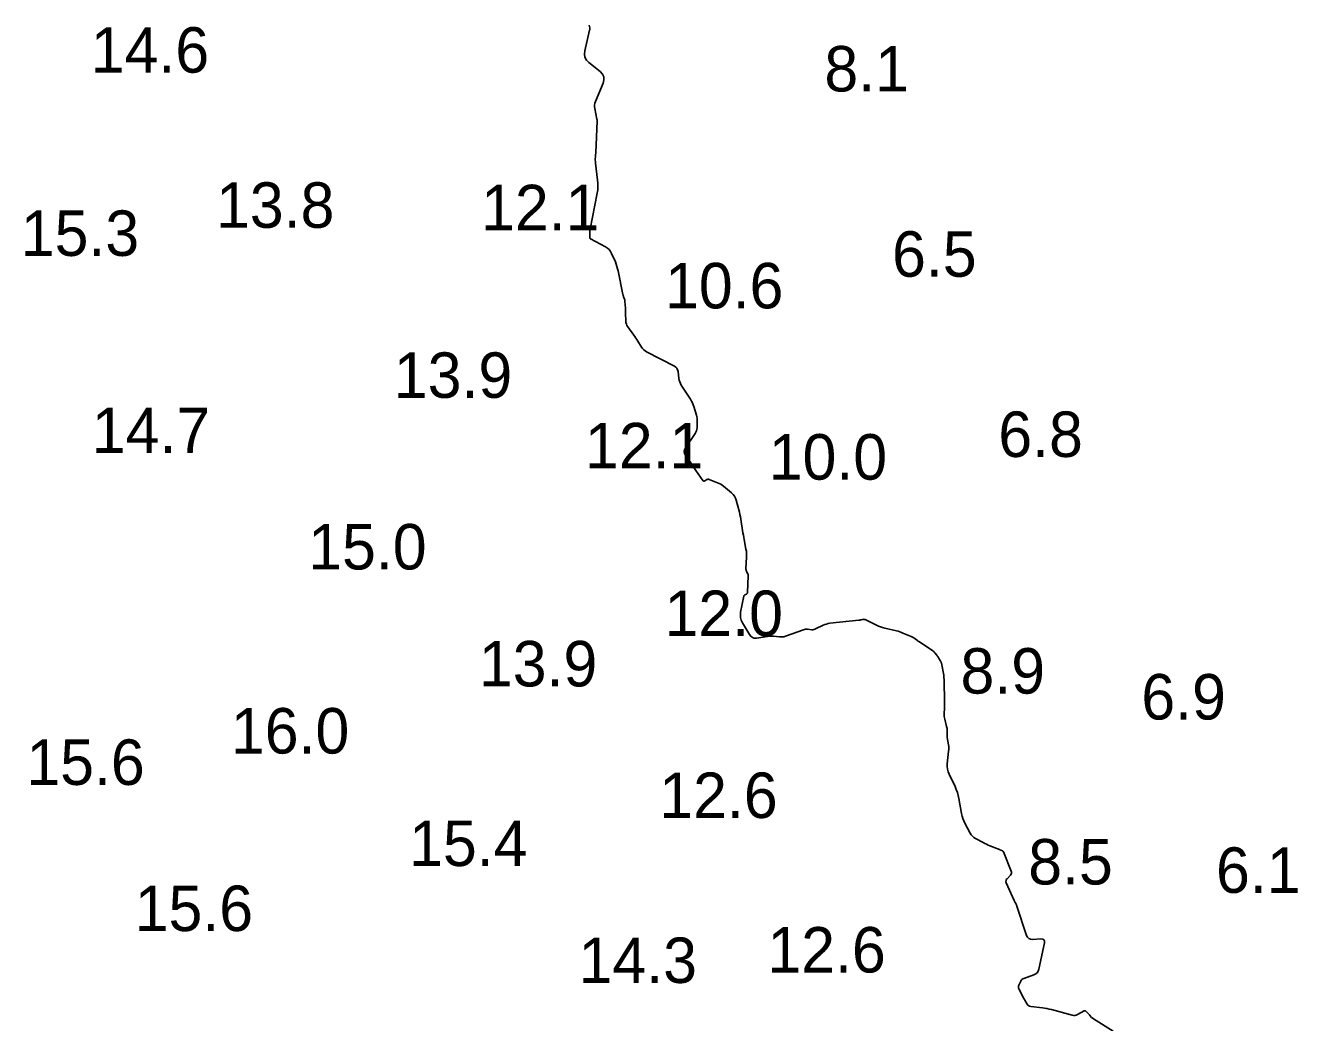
# Model space of a CAD drawing. Extents: x 815352 to 820877, y 582403 to 597439.
# Drawn here: x 819803.4 to 819943.3, y 593298.9 to 593408.5 of the extents above; entities that cross this region are included whole.
import ezdxf

# ---------------------------------------------------------------- set-up
doc = ezdxf.new("R2010")
doc.units = 0
doc.layers.add('V-CONT-EL12', color=7, linetype='Continuous')
doc.layers.add('V-TOPO-SOUN', color=7, linetype='Continuous')

msp = doc.modelspace()

# ---------------------------------------------------------------- linework, layer by layer
at = {"layer": 'V-CONT-EL12'}
msp.add_lwpolyline([(819922.98, 593297.92), (819920.83, 593299.27), (819920.77, 593299.31), (819920.72, 593299.35), (819920.66, 593299.4), (819920.62, 593299.45), (819920.43, 593299.66), (819920.39, 593299.71), (819920.34, 593299.76), (819920.29, 593299.82), (819920.25, 593299.87), (819920.02, 593300.11), (819919.96, 593300.16), (819919.91, 593300.18), (819919.84, 593300.18), (819919.78, 593300.15), (819919.07, 593299.75), (819918.93, 593299.69), (819918.78, 593299.65), (819918.63, 593299.65), (819918.48, 593299.68), (819916.21, 593300.3), (819915.96, 593300.36), (819915.71, 593300.42), (819915.45, 593300.46), (819915.2, 593300.5), (819913.92, 593300.65), (819913.8, 593300.68), (819913.7, 593300.73), (819913.61, 593300.8), (819913.54, 593300.9), (819913.28, 593301.33), (819913.22, 593301.43), (819913.15, 593301.54), (819913.09, 593301.65), (819913.04, 593301.76), (819912.62, 593302.57), (819912.58, 593302.67), (819912.57, 593302.78), (819912.58, 593302.89), (819912.62, 593303), (819912.82, 593303.43), (819912.88, 593303.53), (819912.95, 593303.62), (819913.04, 593303.68), (819913.15, 593303.73), (819914.27, 593304.12), (819914.47, 593304.22), (819914.63, 593304.35), (819914.74, 593304.53), (819914.81, 593304.74), (819915.43, 593307.64), (819915.44, 593307.84), (819915.38, 593307.98), (819915.25, 593308.06), (819915.05, 593308.08), (819914.1, 593308.02), (819913.88, 593308.03), (819913.7, 593308.11), (819913.57, 593308.25), (819913.47, 593308.44), (819912.41, 593311.66), (819912.39, 593311.72), (819912.37, 593311.77), (819912.35, 593311.83), (819912.32, 593311.88), (819912.22, 593312.08), (819912.19, 593312.14), (819912.16, 593312.19), (819912.14, 593312.24), (819912.11, 593312.29), (819911.24, 593314.25), (819911.2, 593314.37), (819911.21, 593314.49), (819911.24, 593314.6), (819911.32, 593314.7), (819911.7, 593315.09), (819911.78, 593315.19), (819911.82, 593315.3), (819911.82, 593315.42), (819911.79, 593315.54), (819910.93, 593317.64), (819910.91, 593317.68), (819910.88, 593317.71), (819910.85, 593317.74), (819910.81, 593317.76), (819910.65, 593317.83), (819910.61, 593317.85), (819910.57, 593317.87), (819910.53, 593317.88), (819910.48, 593317.9), (819909.43, 593318.32), (819909.24, 593318.39), (819909.06, 593318.48), (819908.87, 593318.56), (819908.69, 593318.66), (819907.86, 593319.11), (819907.67, 593319.22), (819907.51, 593319.37), (819907.37, 593319.53), (819907.25, 593319.72), (819906.68, 593320.82), (819906.56, 593321.07), (819906.46, 593321.33), (819906.38, 593321.59), (819906.32, 593321.87), (819906.03, 593323.5), (819905.95, 593323.84), (819905.86, 593324.18), (819905.74, 593324.5), (819905.6, 593324.82), (819904.94, 593326.19), (819904.83, 593326.46), (819904.76, 593326.74), (819904.74, 593327.02), (819904.75, 593327.31), (819904.9, 593328.73), (819904.92, 593328.9), (819904.92, 593329.07), (819904.91, 593329.24), (819904.88, 593329.41), (819904.74, 593330.24), (819904.73, 593330.34), (819904.72, 593330.44), (819904.72, 593330.54), (819904.72, 593330.64), (819904.73, 593331.03), (819904.73, 593331.13), (819904.72, 593331.23), (819904.71, 593331.33), (819904.68, 593331.43), (819904.47, 593332.23), (819904.44, 593332.37), (819904.41, 593332.52), (819904.4, 593332.68), (819904.4, 593332.83), (819904.43, 593333.44), (819904.43, 593333.59), (819904.44, 593333.75), (819904.44, 593333.9), (819904.44, 593334.05), (819904.39, 593336.58), (819904.39, 593336.62), (819904.39, 593336.66), (819904.38, 593336.7), (819904.38, 593336.74), (819904.38, 593336.9), (819904.38, 593336.94), (819904.37, 593336.98), (819904.37, 593337.02), (819904.36, 593337.06), (819904.1, 593338.38), (819904.08, 593338.46), (819904.06, 593338.54), (819904.02, 593338.62), (819903.98, 593338.7), (819903.8, 593339), (819903.75, 593339.07), (819903.7, 593339.14), (819903.65, 593339.21), (819903.6, 593339.28), (819903.38, 593339.55), (819903.32, 593339.62), (819903.26, 593339.68), (819903.2, 593339.73), (819903.13, 593339.78), (819901.63, 593340.78), (819901.56, 593340.82), (819901.49, 593340.87), (819901.42, 593340.92), (819901.35, 593340.97), (819901.08, 593341.17), (819901.01, 593341.22), (819900.94, 593341.26), (819900.86, 593341.3), (819900.79, 593341.34), (819899.88, 593341.71), (819899.71, 593341.78), (819899.53, 593341.85), (819899.34, 593341.9), (819899.16, 593341.95), (819897.88, 593342.25), (819897.64, 593342.32), (819897.4, 593342.39), (819897.17, 593342.48), (819896.95, 593342.58), (819895.71, 593343.18), (819895.65, 593343.2), (819895.6, 593343.21), (819895.54, 593343.22), (819895.48, 593343.21), (819895.25, 593343.15), (819895.19, 593343.14), (819895.13, 593343.13), (819895.07, 593343.12), (819895.01, 593343.11), (819891.83, 593342.78), (819891.64, 593342.75), (819891.46, 593342.7), (819891.28, 593342.64), (819891.1, 593342.57), (819890.28, 593342.16), (819890.18, 593342.12), (819890.07, 593342.09), (819889.96, 593342.08), (819889.85, 593342.08), (819889.4, 593342.12), (819889.28, 593342.12), (819889.17, 593342.12), (819889.06, 593342.1), (819888.96, 593342.06), (819886.95, 593341.36), (819886.79, 593341.31), (819886.64, 593341.29), (819886.48, 593341.28), (819886.31, 593341.28), (819885.66, 593341.35), (819885.49, 593341.36), (819885.33, 593341.36), (819885.17, 593341.35), (819885, 593341.33), (819883.78, 593341.16), (819883.53, 593341.16), (819883.32, 593341.22), (819883.14, 593341.35), (819883, 593341.54), (819882.23, 593342.84), (819882.1, 593343.12), (819882.02, 593343.4), (819882, 593343.7), (819882.03, 593344), (819882.37, 593345.75), (819882.39, 593345.8), (819882.41, 593345.84), (819882.44, 593345.88), (819882.49, 593345.91), (819882.68, 593346), (819882.72, 593346.03), (819882.75, 593346.06), (819882.77, 593346.11), (819882.77, 593346.16), (819882.86, 593348), (819882.86, 593348.07), (819882.85, 593348.14), (819882.83, 593348.21), (819882.8, 593348.27), (819882.67, 593348.53), (819882.64, 593348.59), (819882.63, 593348.66), (819882.62, 593348.73), (819882.62, 593348.8), (819882.69, 593350.04), (819882.69, 593350.27), (819882.68, 593350.49), (819882.66, 593350.72), (819882.62, 593350.95), (819882.42, 593351.98), (819882.37, 593352.23), (819882.33, 593352.48), (819882.29, 593352.72), (819882.25, 593352.97), (819882.09, 593353.99), (819882.05, 593354.24), (819882, 593354.49), (819881.95, 593354.74), (819881.89, 593354.99), (819881.55, 593356.31), (819881.47, 593356.54), (819881.35, 593356.76), (819881.21, 593356.95), (819881.03, 593357.12), (819880.14, 593357.86), (819879.99, 593357.97), (819879.84, 593358.07), (819879.67, 593358.16), (819879.5, 593358.24), (819878.59, 593358.6), (819878.52, 593358.62), (819878.46, 593358.62), (819878.39, 593358.61), (819878.33, 593358.58), (819878.08, 593358.45), (819878.02, 593358.42), (819877.97, 593358.42), (819877.92, 593358.45), (819877.88, 593358.49), (819877.11, 593359.59), (819876.97, 593359.8), (819876.83, 593360), (819876.69, 593360.2), (819876.55, 593360.41), (819875.97, 593361.24), (819875.86, 593361.45), (819875.82, 593361.66), (819875.86, 593361.87), (819875.96, 593362.08), (819877.02, 593363.65), (819877.11, 593363.8), (819877.18, 593363.95), (819877.22, 593364.12), (819877.24, 593364.29), (819877.27, 593364.99), (819877.27, 593365.16), (819877.26, 593365.33), (819877.23, 593365.5), (819877.19, 593365.67), (819876.9, 593366.61), (819876.83, 593366.82), (819876.74, 593367.02), (819876.64, 593367.22), (819876.53, 593367.41), (819875.51, 593368.97), (819875.42, 593369.14), (819875.34, 593369.32), (819875.29, 593369.5), (819875.25, 593369.7), (819875.16, 593370.48), (819875.11, 593370.67), (819875.03, 593370.82), (819874.92, 593370.95), (819874.76, 593371.06), (819871.7, 593372.63), (819871.53, 593372.73), (819871.39, 593372.85), (819871.26, 593372.99), (819871.14, 593373.14), (819870.73, 593373.81), (819870.63, 593373.98), (819870.52, 593374.14), (819870.41, 593374.3), (819870.3, 593374.46), (819869.64, 593375.38), (819869.54, 593375.53), (819869.47, 593375.69), (819869.43, 593375.86), (819869.41, 593376.04), (819869.39, 593376.83), (819869.38, 593376.98), (819869.38, 593377.13), (819869.37, 593377.28), (819869.36, 593377.43), (819869.32, 593378.18), (819869.32, 593378.25), (819869.31, 593378.31), (819869.29, 593378.38), (819869.27, 593378.44), (819869.17, 593378.69), (819869.14, 593378.76), (819869.12, 593378.82), (819869.11, 593378.89), (819869.09, 593378.95), (819868.56, 593381.52), (819868.51, 593381.77), (819868.43, 593382.02), (819868.35, 593382.27), (819868.26, 593382.51), (819867.85, 593383.46), (819867.73, 593383.68), (819867.58, 593383.87), (819867.4, 593384.04), (819867.18, 593384.18), (819865.53, 593385.06), (819865.5, 593385.08), (819865.49, 593385.09), (819865.48, 593385.12), (819865.47, 593385.14), (819865.47, 593385.25), (819865.46, 593385.28), (819865.46, 593385.31), (819865.46, 593385.34), (819865.46, 593385.36), (819865.46, 593385.8), (819865.46, 593385.88), (819865.47, 593385.97), (819865.48, 593386.05), (819865.49, 593386.13), (819866.26, 593390.07), (819866.32, 593390.43), (819866.34, 593390.79), (819866.34, 593391.16), (819866.31, 593391.52), (819866.07, 593393.38), (819866.06, 593393.55), (819866.05, 593393.72), (819866.05, 593393.88), (819866.06, 593394.05), (819866.11, 593394.72), (819866.13, 593394.89), (819866.14, 593395.06), (819866.15, 593395.23), (819866.15, 593395.4), (819866.26, 593397.98), (819866.26, 593398), (819866.26, 593398.02), (819866.26, 593398.04), (819866.25, 593398.06), (819866.25, 593398.15), (819866.25, 593398.17), (819866.24, 593398.19), (819866.24, 593398.21), (819866.24, 593398.23), (819865.99, 593399.38), (819865.96, 593399.57), (819865.96, 593399.77), (819866, 593399.96), (819866.06, 593400.15), (819866.91, 593402.18), (819867.01, 593402.54), (819866.98, 593402.87), (819866.85, 593403.17), (819866.59, 593403.44), (819865.33, 593404.45), (819865.07, 593404.72), (819864.9, 593405.02), (819864.85, 593405.36), (819864.89, 593405.74), (819865.43, 593407.99), (819865.45, 593408.06), (819865.45, 593408.13), (819865.45, 593408.19), (819865.44, 593408.26), (819865.37, 593408.54)], dxfattribs=at)

# ---------------------------------------------------------------- texts
at = {"layer": 'V-TOPO-SOUN'}
for s, p in [('14.6 ', (819810.59, 593403.33)), ('8.1', (819891.24, 593401.26)), ('13.8 ', (819824.36, 593386.27)), ('12.1 ', (819853.5, 593386)), ('15.3 ', (819802.9, 593383.18)), ('6.5', (819898.68, 593380.89)), ('10.6 ', (819873.72, 593377.41)), ('13.9 ', (819843.91, 593367.57)), ('14.7 ', (819810.71, 593361.5)), ('6.8', (819910.36, 593361.07)), ('12.1 ', (819864.92, 593359.82)), ('10.0 ', (819885.12, 593358.58)), ('15.0 ', (819834.5, 593348.7)), ('12.0 ', (819873.67, 593341.38)), ('13.9 ', (819853.26, 593335.84)), ('8.9', (819906.2, 593335.05)), ('6.9', (819926.08, 593332.2)), ('16.0 ', (819826, 593328.46)), ('15.6 ', (819803.51, 593325.01)), ('12.6 ', (819873.09, 593321.37)), ('15.4 ', (819845.59, 593316.09)), ('8.5', (819913.65, 593314.06)), ('6.1', (819934.29, 593313.14)), ('15.6 ', (819815.42, 593308.94)), ('12.6 ', (819884.97, 593304.38)), ('14.3 ', (819864.22, 593303.23))]:
    msp.add_text(s, height=5, dxfattribs=at).set_placement(p)

doc.saveas('drawing.dxf')
